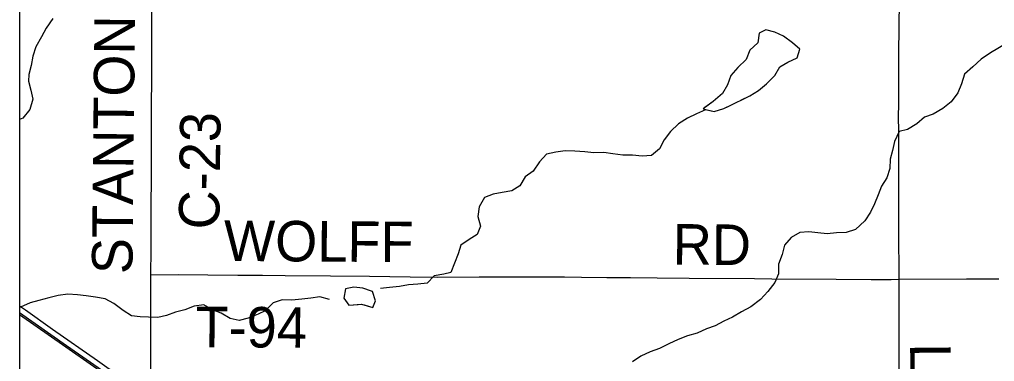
# Model space of a CAD drawing. Extents: x 0 to 34, y 0 to 22.
# Drawn here: x 2.1 to 2.784, y 17.545 to 17.785 of the extents above; entities that cross this region are included whole.
import ezdxf

# ---------------------------------------------------------------- set-up
doc = ezdxf.new("R2010")
doc.units = 0
for name, color, linetype in [('GM_X_County_Road', 7, 'Continuous'), ('GM_X_County_Road_Text', 7, 'Continuous'), ('GM_X_Minor_Lake', 7, 'Continuous'), ('GM_X_Minor_River', 7, 'Continuous'), ('GM_X_Rail_Line', 7, 'Continuous'), ('GM_X_Rail_Line_Text', 7, 'Continuous'), ('GM_X_State_Route', 7, 'Continuous'), ('GM_X_Township_Road', 7, 'Continuous'), ('GM_X_Township_Road_Text', 7, 'Continuous'), ('SH_Cut_Line', 7, 'Continuous'), ('SH_Data', 7, 'Continuous')]:
    doc.layers.add(name, color=color, linetype=linetype)

msp = doc.modelspace()

# ---------------------------------------------------------------- linework, layer by layer
at = {"layer": 'GM_X_County_Road'}
for points in [[(2.19186, 17.51934), (2.19199, 17.53413), (2.19217, 17.56358), (2.19211, 17.5841), (2.19201, 17.60586), (2.19223, 17.62347), (2.19241, 17.64369), (2.19247, 17.68411), (2.19259, 17.70522), (2.19265, 17.72454), (2.19283, 17.74308), (2.19277, 17.75288), (2.19271, 17.77579), (2.19283, 17.79086), (2.19289, 17.79241), (2.19307, 17.79373), (2.19342, 17.79465), (2.19409, 17.79576), (2.19487, 17.79672), (2.19555, 17.7974), (2.19586, 17.79765)], [(2.71675, 17.5234), (2.71665, 17.60276), (2.71659, 17.63737), (2.71645, 17.71015), (2.71634, 17.71316), (2.71637, 17.71695), (2.71645, 17.72567), (2.71657, 17.73499), (2.71646, 17.75784), (2.71679, 17.78279), (2.7169, 17.79478)]]:
    msp.add_lwpolyline(points, dxfattribs=at)
at = {"layer": 'GM_X_Minor_Lake'}
for points in [[(2.59688, 17.72403), (2.61198, 17.73142), (2.61805, 17.73506), (2.62372, 17.73983), (2.62959, 17.74575), (2.63298, 17.75165), (2.63867, 17.75509), (2.64511, 17.75797), (2.64717, 17.76406), (2.64202, 17.76861), (2.63573, 17.77334), (2.62964, 17.77598), (2.62336, 17.77767), (2.61862, 17.77537), (2.6177, 17.76852), (2.61203, 17.76337), (2.6094, 17.7569), (2.60353, 17.75136), (2.59862, 17.74564), (2.59637, 17.73917), (2.59278, 17.73307), (2.58635, 17.72753), (2.57928, 17.72225)], [(2.60573, 17.72836), (2.61198, 17.73142), (2.61805, 17.73506), (2.62372, 17.73983), (2.62959, 17.74575), (2.63298, 17.75165), (2.63867, 17.75509), (2.64511, 17.75797), (2.64717, 17.76406), (2.64202, 17.76861), (2.63573, 17.77334), (2.62964, 17.77598), (2.62336, 17.77767), (2.61862, 17.77537), (2.6177, 17.76852), (2.61203, 17.76337), (2.6094, 17.7569), (2.60353, 17.75136), (2.59862, 17.74564), (2.59637, 17.73917), (2.59278, 17.73307), (2.58635, 17.72753), (2.58048, 17.72314)], [(2.58105, 17.72181), (2.58714, 17.72031), (2.59378, 17.72261), (2.59966, 17.7253)], [(2.57928, 17.72225), (2.58714, 17.72031), (2.59378, 17.72261), (2.59688, 17.72403)], [(2.34749, 17.59413), (2.34069, 17.59645), (2.33441, 17.59719), (2.32853, 17.59603), (2.32742, 17.58937), (2.33086, 17.58444), (2.33983, 17.58524)], [(2.34678, 17.59438), (2.34069, 17.59645), (2.33441, 17.59719), (2.32853, 17.59603), (2.32742, 17.58937), (2.33086, 17.58444), (2.33751, 17.58503)], [(2.33983, 17.58524), (2.34778, 17.58278), (2.34966, 17.58754), (2.34749, 17.59413)], [(2.34169, 17.58466), (2.34778, 17.58278), (2.34966, 17.58754), (2.34754, 17.594)]]:
    msp.add_lwpolyline(points, dxfattribs=at)
at = {"layer": 'GM_X_Minor_River'}
for points in [[(2.12339, 17.78567), (2.11867, 17.779), (2.11547, 17.77271), (2.11151, 17.76585), (2.10945, 17.75919), (2.10815, 17.75272), (2.10647, 17.74644), (2.1063, 17.74168), (2.10785, 17.73541)], [(2.79214, 17.76835), (2.78077, 17.76147), (2.77433, 17.75707), (2.76846, 17.75173), (2.76259, 17.74658), (2.76053, 17.73991), (2.7579, 17.73344), (2.75318, 17.72715), (2.74731, 17.72256), (2.74049, 17.71855), (2.73442, 17.71644), (2.72912, 17.71185), (2.72268, 17.70784), (2.71679, 17.7063), (2.7134, 17.69944), (2.7121, 17.69297), (2.71042, 17.68688), (2.71026, 17.68041), (2.70801, 17.67394), (2.70424, 17.66803), (2.70198, 17.66194), (2.69935, 17.65566), (2.69653, 17.64975), (2.69276, 17.64366), (2.68614, 17.63755), (2.67968, 17.63543), (2.67284, 17.63522), (2.6662, 17.63463), (2.65973, 17.63518), (2.65346, 17.63592), (2.647, 17.63552), (2.64094, 17.63188), (2.6364, 17.62654), (2.63472, 17.62007), (2.63209, 17.61322), (2.63212, 17.60656), (2.62968, 17.60028), (2.62477, 17.59399), (2.61947, 17.58845), (2.61285, 17.5833), (2.60621, 17.57985), (2.59996, 17.57603), (2.59389, 17.57316), (2.58764, 17.57009), (2.58156, 17.56779), (2.57512, 17.56473), (2.56829, 17.56299), (2.56184, 17.5605), (2.5552, 17.55743), (2.54876, 17.55399), (2.54212, 17.55169), (2.53567, 17.54881), (2.5298, 17.5448)], [(2.10785, 17.73541), (2.1094, 17.72895), (2.10734, 17.72191), (2.10243, 17.71581), (2.1, 17.71474)], [(2.58105, 17.72162), (2.57461, 17.71875), (2.56835, 17.71568), (2.5621, 17.71167), (2.55642, 17.70633), (2.55208, 17.70042), (2.54869, 17.69413), (2.54301, 17.68955), (2.53655, 17.68895), (2.52989, 17.68969), (2.52305, 17.68967), (2.51602, 17.6906), (2.50956, 17.69152), (2.50272, 17.69131), (2.49625, 17.69205), (2.48941, 17.6926), (2.48257, 17.69276), (2.47611, 17.69179), (2.46947, 17.69044), (2.46455, 17.6851), (2.46021, 17.67862), (2.45453, 17.6746), (2.45076, 17.66832), (2.44526, 17.66469), (2.43843, 17.66352), (2.43216, 17.66236), (2.4259, 17.66006), (2.42232, 17.65358), (2.4214, 17.64673), (2.42314, 17.63989), (2.42089, 17.63399), (2.41521, 17.63055), (2.40933, 17.62653), (2.40765, 17.62044), (2.40239, 17.6075), (2.39746, 17.60634), (2.39081, 17.60518), (2.3857, 17.60002), (2.37924, 17.59924), (2.37279, 17.59865), (2.36633, 17.59768), (2.35949, 17.59689), (2.35304, 17.59611)], [(2.31735, 17.58838), (2.3105, 17.59026), (2.30423, 17.58929), (2.29797, 17.5887), (2.29094, 17.5881), (2.2841, 17.58827), (2.27784, 17.58616), (2.27235, 17.58044), (2.26742, 17.57814), (2.2604, 17.57545), (2.25395, 17.57372), (2.24767, 17.57522), (2.24139, 17.57881), (2.2353, 17.58126), (2.2292, 17.58466), (2.22236, 17.58388), (2.21591, 17.58119), (2.20946, 17.57946), (2.20301, 17.57716), (2.19694, 17.57581), (2.19048, 17.57617), (2.18458, 17.57634), (2.1785, 17.57689), (2.17259, 17.58086), (2.16611, 17.58559), (2.16001, 17.58899), (2.15336, 17.59011), (2.1467, 17.59104), (2.14062, 17.59178), (2.13378, 17.59232), (2.12713, 17.59135), (2.12049, 17.58962), (2.11347, 17.58769), (2.10739, 17.58615), (2.10076, 17.58309), (2.1, 17.58272)]]:
    msp.add_lwpolyline(points, dxfattribs=at)
at = {"layer": 'GM_X_Rail_Line'}
for points in [[(2.17196, 17.52879), (2.13304, 17.55589), (2.1, 17.57901)], [(2.62213, 17.08333), (2.61546, 17.10105), (2.61328, 17.10611), (2.60609, 17.11961), (2.58639, 17.15507), (2.58101, 17.1651), (2.57769, 17.17097), (2.57433, 17.17622), (2.56921, 17.18311), (2.56135, 17.19108), (2.52825, 17.22007), (2.50443, 17.24073), (2.48553, 17.25718), (2.42753, 17.30737), (2.27754, 17.43791), (2.22118, 17.48656), (2.20685, 17.49923), (2.19817, 17.50659), (2.1918, 17.5118), (2.18386, 17.51826), (2.17127, 17.52785), (2.13237, 17.55494), (2.1, 17.57759)]]:
    msp.add_lwpolyline(points, dxfattribs=at)
at = {"layer": 'GM_X_Rail_Line_Text'}
msp.add_lwpolyline([(4.29417, 16.81303), (4.29258, 17.16739), (4.29139, 17.31008), (4.28969, 17.51278), (4.28798, 17.71737), (4.28678, 17.83811), (4.17864, 17.83524), (4.04512, 17.83208), (3.53178, 17.8199), (3.04126, 17.80913), (2.77875, 17.80661), (2.75328, 17.8059), (2.73257, 17.80595), (2.72272, 17.80515), (2.29055, 17.79989), (2.19668, 17.79909), (2.1, 17.79837), (2.1, 15.5976)], dxfattribs=at)
at = {"layer": 'GM_X_State_Route'}
msp.add_lwpolyline([(2.19186, 17.51934), (2.17001, 17.53446), (2.15457, 17.54543), (2.12322, 17.56731), (2.10412, 17.5809), (2.1, 17.58378)], dxfattribs=at)
at = {"layer": 'GM_X_Township_Road'}
msp.add_lwpolyline([(2.19201, 17.60586), (2.21146, 17.60592), (2.23213, 17.60575), (2.25314, 17.60557), (2.27044, 17.60545), (2.28629, 17.60528), (2.3181, 17.60499), (2.34544, 17.60476), (2.37394, 17.60435), (2.39316, 17.60424), (2.42218, 17.60429), (2.45527, 17.60441), (2.48207, 17.60426), (2.49412, 17.60412), (2.51172, 17.60398), (2.52828, 17.60384), (2.54717, 17.6037), (2.56941, 17.60347), (2.61534, 17.60314), (2.62744, 17.60305), (2.67262, 17.60263), (2.697, 17.60249), (2.71114, 17.60259), (2.71665, 17.60276), (2.76403, 17.60286), (2.78656, 17.60288)], dxfattribs=at)
at = {"layer": 'SH_Cut_Line'}
msp.add_lwpolyline([(2.99803, 20.39937), (2.65087, 20.39662), (2.57356, 20.39618), (2.22745, 20.39495), (2.18926, 20.39483), (2.1, 20.39416), (2.1, 14.1)], dxfattribs=at)
at = {"layer": 'SH_Data'}
msp.add_line((2.1, 20.9), (2.1, 14.1), dxfattribs=at)

# ---------------------------------------------------------------- texts
at = {"layer": 'GM_X_County_Road_Text'}
for s, rotation, p in [('STANTON', 89.4109, (2.17911, 17.60616)), ('C-23', 89.31422, (2.24006, 17.63753)), ('LESTER', 270.56055, (2.72438, 17.55763))]:
    msp.add_text(s, height=0.028409, rotation=rotation, dxfattribs=at).set_placement(p)
at = {"layer": 'GM_X_Township_Road_Text'}
for s, rotation, p in [('WOLFF', 359.59388, (2.24329, 17.61555)), ('RD', 359.50448, (2.55788, 17.61305)), ('T-94', 359.64652, (2.22332, 17.55507))]:
    msp.add_text(s, height=0.028409, rotation=rotation, dxfattribs=at).set_placement(p)

doc.saveas('drawing.dxf')
